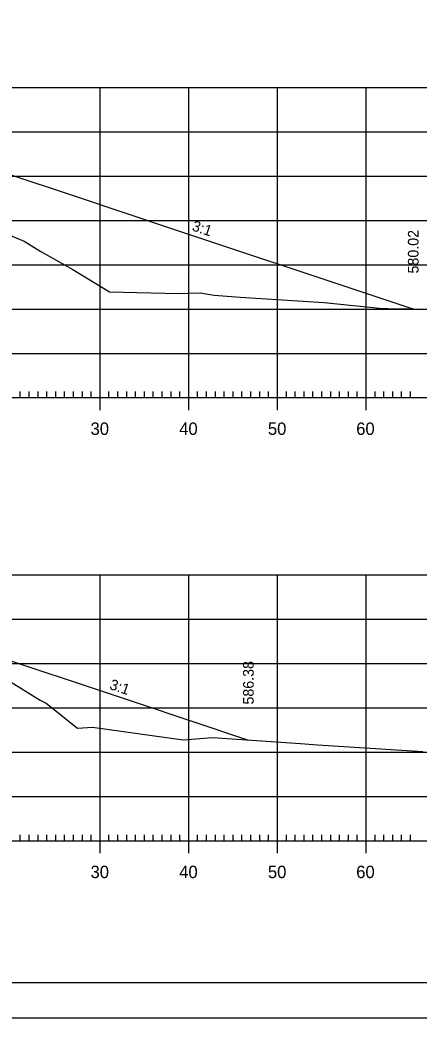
# Model space of a CAD drawing. Extents: x 961436 to 1372525, y 380079 to 2027791.
# Drawn here: x 1370654.8 to 1370699.8, y 380322.4 to 380435 of the extents above; entities that cross this region are included whole.
import ezdxf

# ---------------------------------------------------------------- set-up
doc = ezdxf.new("R2010")
doc.units = 0
for name, color, linetype in [('R_Axis', 7, 'Continuous'), ('R_Axis Annot', 7, 'Continuous'), ('R_Exist Surface', 7, 'Continuous'), ('R_Fin Surface', 7, 'Continuous'), ('R_Fin Surface Annot', 7, 'Continuous'), ('R_Grid', 7, 'Continuous'), ('R_No Plot', 7, 'Continuous')]:
    doc.layers.add(name, color=color, linetype=linetype)

msp = doc.modelspace()

# ---------------------------------------------------------------- linework, layer by layer
at = {"layer": 'R_Axis'}
for p, q in [((1370654.81, 380392.4), (1370654.81, 380393.1)), ((1370655.81, 380392.4), (1370655.81, 380393.1)), ((1370656.81, 380392.4), (1370656.81, 380393.1)), ((1370657.81, 380392.4), (1370657.81, 380393.1)), ((1370658.81, 380392.4), (1370658.81, 380393.1)), ((1370659.81, 380392.4), (1370659.81, 380393.1)), ((1370660.81, 380392.4), (1370660.81, 380393.1)), ((1370661.81, 380392.4), (1370661.81, 380393.1)), ((1370662.81, 380392.4), (1370662.81, 380393.1)), ((1370663.81, 380391), (1370663.81, 380393.8)), ((1370664.81, 380392.4), (1370664.81, 380393.1)), ((1370665.81, 380392.4), (1370665.81, 380393.1)), ((1370666.81, 380392.4), (1370666.81, 380393.1)), ((1370667.81, 380392.4), (1370667.81, 380393.1)), ((1370668.81, 380392.4), (1370668.81, 380393.1)), ((1370669.81, 380392.4), (1370669.81, 380393.1)), ((1370670.81, 380392.4), (1370670.81, 380393.1)), ((1370671.81, 380392.4), (1370671.81, 380393.1)), ((1370672.81, 380392.4), (1370672.81, 380393.1)), ((1370673.81, 380391), (1370673.81, 380393.8)), ((1370674.81, 380392.4), (1370674.81, 380393.1)), ((1370675.81, 380392.4), (1370675.81, 380393.1)), ((1370676.81, 380392.4), (1370676.81, 380393.1)), ((1370677.81, 380392.4), (1370677.81, 380393.1)), ((1370678.81, 380392.4), (1370678.81, 380393.1)), ((1370679.81, 380392.4), (1370679.81, 380393.1)), ((1370680.81, 380392.4), (1370680.81, 380393.1)), ((1370681.81, 380392.4), (1370681.81, 380393.1)), ((1370682.81, 380392.4), (1370682.81, 380393.1)), ((1370683.81, 380391), (1370683.81, 380393.8)), ((1370684.81, 380392.4), (1370684.81, 380393.1)), ((1370685.81, 380392.4), (1370685.81, 380393.1)), ((1370686.81, 380392.4), (1370686.81, 380393.1)), ((1370687.81, 380392.4), (1370687.81, 380393.1)), ((1370688.81, 380392.4), (1370688.81, 380393.1)), ((1370689.81, 380392.4), (1370689.81, 380393.1)), ((1370690.81, 380392.4), (1370690.81, 380393.1)), ((1370691.81, 380392.4), (1370691.81, 380393.1)), ((1370692.81, 380392.4), (1370692.81, 380393.1)), ((1370693.81, 380391), (1370693.81, 380393.8)), ((1370694.81, 380392.4), (1370694.81, 380393.1)), ((1370695.81, 380392.4), (1370695.81, 380393.1)), ((1370696.81, 380392.4), (1370696.81, 380393.1)), ((1370697.81, 380392.4), (1370697.81, 380393.1)), ((1370698.81, 380392.4), (1370698.81, 380393.1)), ((1370493.81, 380392.4), (1370773.81, 380392.4)), ((1370663.81, 380341), (1370663.81, 380343.8)), ((1370673.81, 380341), (1370673.81, 380343.8)), ((1370683.81, 380341), (1370683.81, 380343.8)), ((1370693.81, 380341), (1370693.81, 380343.8)), ((1370493.81, 380342.4), (1370773.81, 380342.4)), ((1370654.81, 380342.4), (1370654.81, 380343.1)), ((1370655.81, 380342.4), (1370655.81, 380343.1)), ((1370656.81, 380342.4), (1370656.81, 380343.1)), ((1370657.81, 380342.4), (1370657.81, 380343.1)), ((1370658.81, 380342.4), (1370658.81, 380343.1)), ((1370659.81, 380342.4), (1370659.81, 380343.1)), ((1370660.81, 380342.4), (1370660.81, 380343.1)), ((1370661.81, 380342.4), (1370661.81, 380343.1)), ((1370662.81, 380342.4), (1370662.81, 380343.1)), ((1370664.81, 380342.4), (1370664.81, 380343.1)), ((1370665.81, 380342.4), (1370665.81, 380343.1)), ((1370666.81, 380342.4), (1370666.81, 380343.1)), ((1370667.81, 380342.4), (1370667.81, 380343.1)), ((1370668.81, 380342.4), (1370668.81, 380343.1)), ((1370669.81, 380342.4), (1370669.81, 380343.1)), ((1370670.81, 380342.4), (1370670.81, 380343.1)), ((1370671.81, 380342.4), (1370671.81, 380343.1)), ((1370672.81, 380342.4), (1370672.81, 380343.1)), ((1370674.81, 380342.4), (1370674.81, 380343.1)), ((1370675.81, 380342.4), (1370675.81, 380343.1)), ((1370676.81, 380342.4), (1370676.81, 380343.1)), ((1370677.81, 380342.4), (1370677.81, 380343.1)), ((1370678.81, 380342.4), (1370678.81, 380343.1)), ((1370679.81, 380342.4), (1370679.81, 380343.1)), ((1370680.81, 380342.4), (1370680.81, 380343.1)), ((1370681.81, 380342.4), (1370681.81, 380343.1)), ((1370682.81, 380342.4), (1370682.81, 380343.1)), ((1370684.81, 380342.4), (1370684.81, 380343.1)), ((1370685.81, 380342.4), (1370685.81, 380343.1)), ((1370686.81, 380342.4), (1370686.81, 380343.1)), ((1370687.81, 380342.4), (1370687.81, 380343.1)), ((1370688.81, 380342.4), (1370688.81, 380343.1)), ((1370689.81, 380342.4), (1370689.81, 380343.1)), ((1370690.81, 380342.4), (1370690.81, 380343.1)), ((1370691.81, 380342.4), (1370691.81, 380343.1)), ((1370692.81, 380342.4), (1370692.81, 380343.1)), ((1370694.81, 380342.4), (1370694.81, 380343.1)), ((1370695.81, 380342.4), (1370695.81, 380343.1)), ((1370696.81, 380342.4), (1370696.81, 380343.1)), ((1370697.81, 380342.4), (1370697.81, 380343.1)), ((1370698.81, 380342.4), (1370698.81, 380343.1))]:
    msp.add_line(p, q, dxfattribs=at)
at = {"layer": 'R_Exist Surface'}
for points in [[(1370653.71, 380410.68), (1370655.23, 380410.07), (1370657.12, 380408.89), (1370660.73, 380406.85), (1370664.88, 380404.33), (1370672.65, 380404.15), (1370675.08, 380404.21), (1370676.69, 380403.96), (1370679.6, 380403.73), (1370689.07, 380403.13), (1370695.7, 380402.46), (1370696.26, 380402.45), (1370701.11, 380402.39)], [(1370649.68, 380362.81), (1370657.05, 380358.28), (1370657.72, 380357.92), (1370661.27, 380355.13), (1370662.94, 380355.22), (1370673.19, 380353.81), (1370676.47, 380354.05), (1370686.42, 380353.38), (1370688.34, 380353.25), (1370700.21, 380352.47)]]:
    msp.add_lwpolyline(points, dxfattribs=at)
at = {"layer": 'R_Fin Surface'}
for points in [[(1370565.46, 380405.53), (1370569.6, 380404.16), (1370571.67, 380403.47), (1370585.42, 380408.05), (1370597.81, 380412.18), (1370606.53, 380415.09), (1370614.33, 380417.69), (1370617.31, 380418.68), (1370624.81, 380418.98), (1370633.81, 380419.16), (1370642.81, 380418.98), (1370650.31, 380418.68), (1370653.07, 380417.76), (1370661.12, 380415.08), (1370671.96, 380411.46), (1370694.35, 380404), (1370695.57, 380403.59), (1370697.15, 380403.07), (1370698.39, 380402.65), (1370699.12, 380402.41)], [(1370581.41, 380351.88), (1370599.49, 380357.91), (1370614.33, 380362.86), (1370617.31, 380363.85), (1370624.81, 380364.15), (1370633.81, 380364.33), (1370642.81, 380364.15), (1370650.31, 380363.85), (1370653.07, 380362.93), (1370664.15, 380359.24), (1370667.77, 380358.03), (1370680.53, 380353.78)]]:
    msp.add_lwpolyline(points, dxfattribs=at)
at = {"layer": 'R_Grid'}
for p, q in [((1370493.81, 380427.4), (1370773.81, 380427.4)), ((1370663.81, 380392.4), (1370663.81, 380427.4)), ((1370673.81, 380392.4), (1370673.81, 380427.4)), ((1370683.81, 380392.4), (1370683.81, 380427.4)), ((1370693.81, 380392.4), (1370693.81, 380427.4)), ((1370493.81, 380422.4), (1370773.81, 380422.4)), ((1370493.81, 380417.4), (1370773.81, 380417.4)), ((1370493.81, 380412.4), (1370773.81, 380412.4)), ((1370493.81, 380407.4), (1370773.81, 380407.4)), ((1370493.81, 380402.4), (1370773.81, 380402.4)), ((1370493.81, 380397.4), (1370773.81, 380397.4)), ((1370493.81, 380392.4), (1370773.81, 380392.4)), ((1370493.81, 380372.4), (1370773.81, 380372.4)), ((1370663.81, 380342.4), (1370663.81, 380372.4)), ((1370673.81, 380342.4), (1370673.81, 380372.4)), ((1370683.81, 380342.4), (1370683.81, 380372.4)), ((1370693.81, 380342.4), (1370693.81, 380372.4)), ((1370493.81, 380367.4), (1370773.81, 380367.4)), ((1370493.81, 380362.4), (1370773.81, 380362.4)), ((1370493.81, 380357.4), (1370773.81, 380357.4)), ((1370493.81, 380352.4), (1370773.81, 380352.4)), ((1370493.81, 380347.4), (1370773.81, 380347.4)), ((1370493.81, 380342.4), (1370773.81, 380342.4))]:
    msp.add_line(p, q, dxfattribs=at)
at = {"layer": 'R_No Plot'}
for p, q in [((1370791.99, 380326.4), (1370475.81, 380326.4)), ((1370463.41, 380322.42), (1370796.74, 380322.42))]:
    msp.add_line(p, q, dxfattribs=at)
for points in [[(1370463.4, 380535.75), (1370796.74, 380535.75), (1370796.74, 380322.41), (1370463.4, 380322.41)], [(1370709.73, 380531.86), (1370729.35, 380531.86), (1370729.35, 380521.98), (1370745.46, 380521.98), (1370768.66, 380521.98), (1370768.78, 380493.82), (1370791.99, 380493.82), (1370791.99, 380326.4), (1370475.81, 380326.4), (1370475.81, 380531.86)]]:
    msp.add_lwpolyline(points, close=True, dxfattribs=at)

# ---------------------------------------------------------------- texts
at = {"layer": 'R_Axis Annot'}
for s, p in [('30', (1370662.73, 380388.2)), ('40', (1370672.73, 380388.2)), ('50', (1370682.73, 380388.2)), ('60', (1370692.69, 380388.2)), ('30', (1370662.73, 380338.2)), ('40', (1370672.73, 380338.2)), ('50', (1370682.73, 380338.2)), ('60', (1370692.69, 380338.2))]:
    msp.add_text(s, height=1.4, dxfattribs=at).set_placement(p)
at = {"layer": 'R_Fin Surface Annot'}
for s, rotation, p in [('3:1', 341.5651, (1370674.08, 380411.29)), ('580.02', 90, (1370699.72, 380406.41)), ('586.38', 90, (1370681.13, 380357.78)), ('3:1', 341.5651, (1370664.79, 380359.55))]:
    msp.add_text(s, height=1.2, rotation=rotation, dxfattribs=at).set_placement(p)

doc.saveas('drawing.dxf')
